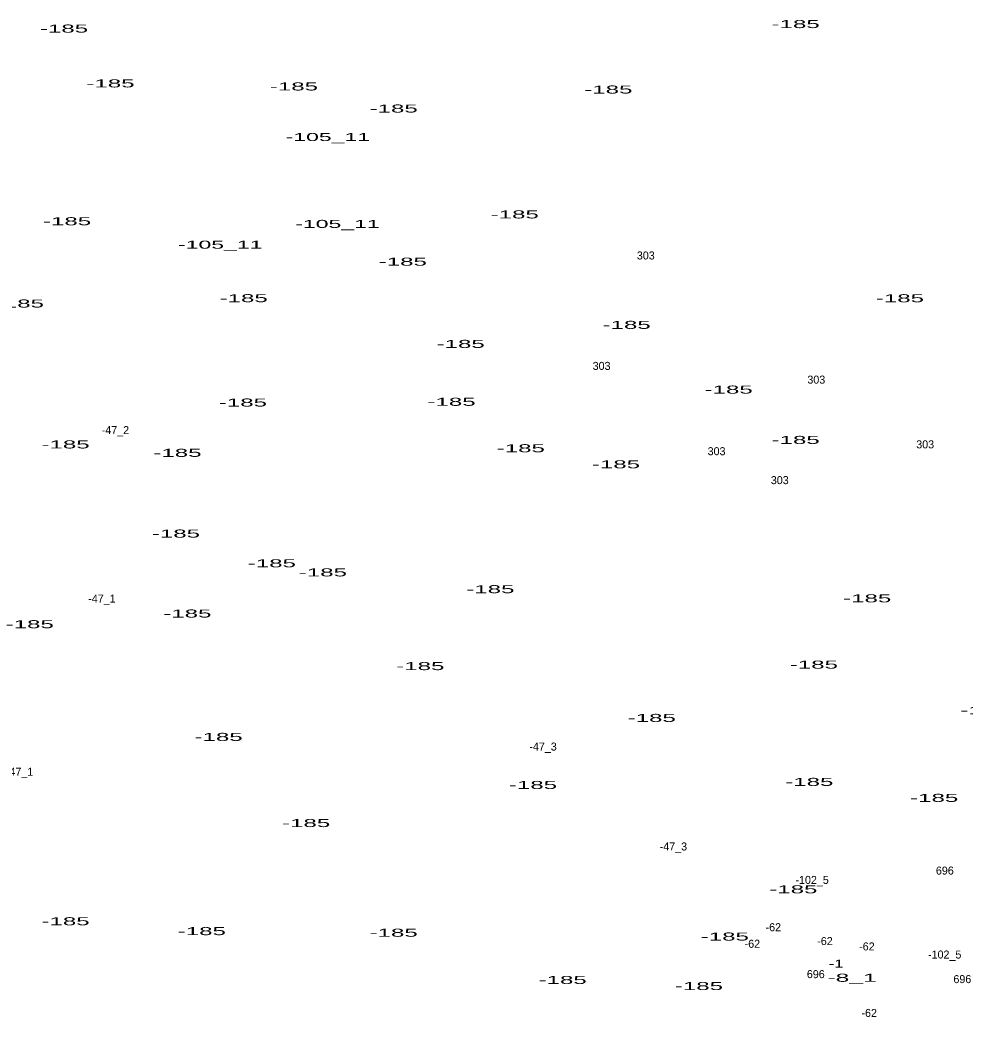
# Model space of a CAD drawing. Extents: x -658595 to -655205, y -1004347 to -1000147.
# Drawn here: x -657460.8 to -656988.6, y -1002230.9 to -1001732.8 of the extents above; entities that cross this region are included whole.
import ezdxf
from ezdxf.enums import TextEntityAlignment as Align

# ---------------------------------------------------------------- set-up
doc = ezdxf.new("R2010")
doc.units = 0
doc.header["$LTSCALE"] = 1.6
doc.layers.add('24', color=7, linetype='Continuous')

msp = doc.modelspace()

# ---------------------------------------------------------------- texts
at = {"layer": '24'}
for s, width, p in [('-185', 2.25, (-657438.801, -1001739.08)), ('-185', 2.25, (-657073.271, -1001736.83)), ('-185', 2.25, (-657415.601, -1001766.47)), ('-185', 2.25, (-657323.931, -1001768)), ('-185', 2.25, (-657166.841, -1001769.53)), ('-185', 2.25, (-657274.101, -1001779.03)), ('-105_11', 2.15, (-657306.99, -1001793.26)), ('-185', 2.25, (-657437.281, -1001835.34)), ('-185', 2.25, (-657213.621, -1001831.92)), ('-105_11', 2.15, (-657302.18, -1001836.67)), ('-105_11', 2.15, (-657360.75, -1001847.04)), ('-185', 2.25, (-657269.551, -1001855.53)), ('-185', 2.25, (-657349.041, -1001873.77)), ('-185', 2.25, (-657021.161, -1001873.81)), ('-185', 2.25, (-657460.861, -1001876.44)), ('-185', 2.25, (-657157.711, -1001887.1)), ('-185', 2.25, (-657240.631, -1001896.61)), ('-185', 2.25, (-657106.741, -1001919.44)), ('-185', 2.25, (-657349.421, -1001925.9)), ('-185', 2.25, (-657245.201, -1001925.53)), ('-185', 2.25, (-657073.271, -1001944.58)), ('-185', 2.25, (-657438.041, -1001946.83)), ('-185', 2.25, (-657210.581, -1001948.74)), ('-185', 2.25, (-657382.131, -1001951.03)), ('-185', 2.25, (-657163.041, -1001956.76)), ('-185', 2.25, (-657382.891, -1001991.37)), ('-185', 2.25, (-657334.961, -1002006.21)), ('-185', 2.25, (-657309.481, -1002010.76)), ('-185', 2.25, (-657225.801, -1002019.14)), ('-185', 2.25, (-657037.521, -1002023.72)), ('-185', 2.25, (-657377.181, -1002031.31)), ('-185', 2.25, (-657455.921, -1002036.64)), ('-185', 2.25, (-657260.791, -1002057.57)), ('-185', 2.25, (-657064.151, -1002056.83)), ('-185', 2.25, (-656978.941, -1002079.66)), ('-185', 2.25, (-657145.161, -1002083.46)), ('-185', 2.25, (-657361.571, -1002092.95)), ('-185', 2.25, (-657204.501, -1002116.95)), ('-185', 2.25, (-657066.431, -1002115.42)), ('-185', 2.25, (-657004.051, -1002123.4)), ('-185', 2.25, (-657317.851, -1002135.98)), ('-185', 2.25, (-657074.421, -1002169.08)), ('-185', 2.25, (-657438.041, -1002185.04)), ('-185', 2.25, (-657369.951, -1002189.98)), ('-185', 2.25, (-657274.111, -1002190.77)), ('-185', 2.25, (-657108.651, -1002192.67)), ('-1', 1.55, (-657053.051, -1002206.22)), ('-185', 2.25, (-657189.671, -1002214.36)), ('-8_1', 2.3, (-657045.081, -1002213.27)), ('-185', 2.25, (-657121.581, -1002217.4))]:
    msp.add_text(s, height=4, dxfattribs=dict(at, width=width)).set_placement(p, align=Align.CENTER)
for s, p in [('303', (-657148.151, -1001852.43)), ('303', (-657170.221, -1001907.6)), ('303', (-657062.951, -1001914.45)), ('-47_2', (-657413.122, -1001939.67)), ('303', (-657112.771, -1001950.22)), ('303', (-657008.551, -1001946.79)), ('303', (-657081.201, -1001964.67)), ('-47_1', (-657419.866, -1002023.86)), ('-47_3', (-657199.472, -1002097.77)), ('-47_1', (-657460.996, -1002110.33)), ('-47_3', (-657134.352, -1002147.68)), ('-102_5', (-657065.04, -1002164.39)), ('696', (-656998.733, -1002159.72)), ('-62', (-657084.43, -1002188.02)), ('-62', (-657094.89, -1002196.28)), ('-62', (-657058.61, -1002194.93)), ('-62', (-657037.68, -1002197.62)), ('-102_5', (-656998.8, -1002201.66)), ('696', (-657063.203, -1002211.46)), ('696', (-656989.983, -1002213.94)), ('-62', (-657036.53, -1002230.84))]:
    msp.add_text(s, height=4, dxfattribs=at).set_placement(p, align=Align.CENTER)

doc.saveas('drawing.dxf')
